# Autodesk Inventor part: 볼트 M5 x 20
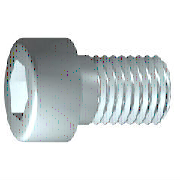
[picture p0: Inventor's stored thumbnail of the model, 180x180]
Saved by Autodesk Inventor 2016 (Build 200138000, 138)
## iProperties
Created: 2012-02
Part Number: 볼트 M5 x 20
Material: 스테인리스강
Description: 6각 소켓 머리 캡 나사
Document SubType Name: Modeling
Standard: ISO 4762
Designer: mduedu
Standard Revision: Fourth edition 2004-03-01
Standards Organization: ISO
Language: ko-KR
Size Designation: M5 x 20
Categories: <MemberInstance><Categories><Category DisplayName="조임쇠" InternalName="e4da775c-781d-43d5-af7c-5136215cf5a6" Mnemonic="FSTN"><Category DisplayName="볼트" InternalN
Density: 8.08 g/cm^3
Mass: 5.10181 g
Surface Area: 5.88237 cm^2
Volume: 0.631412 cm^3
Appearance: 반광택
IsCustomPart: 0
Author: mduedu
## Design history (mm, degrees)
sketch "스케치1"
  geometry: L1 (-1.167, 0)-(20, 0); L2 (20, 0)-(20, 2.5); L3 (20, 2.5)-(2, 2.5); L4 (2, 2.5)-(1.509, 2.5); L5 (1.509, 2.5)-(0, 2.5); L6 (0, 2.5)-(0, 4.25); L7 (0, 4.25)-(-5, 4.25); L8 (-5, 4.25)-(-5, 2.309); L9 (-5, 2.309)-(-2.5, 2.309); L10 (-2.5, 2.309)-(-1.167, 0); L11 (-10, 0)-(25, 0) reference; L12 (0, -0.85)-(0, 5.1) reference; L13 (2, 2.5)-(0, 2.5)
  constraints: 22 end point, 6 parallel, 2 collinear, 2 perpendicular, 1 horizontal, 1 point on line
  dimensions: "d1" = 18 distance from line of L3.end L2 (= GEL); "d2" = 0.49086 distance of L4.end L3.end (computed from GAL); "d3" = 5 distance between parallel lines of L8 L6 (= KOH); "d4" = 2.5 distance of L8.end L9.end (= INTI); "d5" = 60 deg angle of L10 L1; "d6" = 5 diameter of L3 L1 (= GD); "d7" = 5 diameter of L5 L1 (= BDM); "d8" = 4.6188 diameter of L9 L1 (= 1.1547 x SW); "d9" = 8.5 diameter of L7 L1 (= KOD); "d26" = 20 distance between parallel lines of L12 L2 (= NLG)
revolve "본체" sketch "스케치1" stored, may be unused: angle "d10" = 90 deg
sketch "스케치2"
  geometry: L1 (0, -5.95)-(0, 5.95) reference; L2 (-5.95, 0)-(5.95, 0) reference; L3 (2.309, 0)-(1.155, -2); L4 (1.155, -2)-(-1.155, -2); L5 (-1.155, -2)-(-2.309, 0); L6 (-2.309, 0)-(-1.155, 2); L7 (-1.155, 2)-(1.155, 2); L8 (1.155, 2)-(2.309, 0); 2 further points
  constraints: 12 end point, 1 coincident, 1 horizontal alignment, 1 point on line, 12 other
extrude "슬롯" join sketch "스케치2" stored distance "d11" = 10; taper "d12" = 0 deg
workplane "Work Plane1"
fillet "Fillet2" dims "d30" = 0.1 (= R)
body "Solid1"
fillet "모깎기1" dims "d17" = 0.5 (= RR)
feature "스레드" dims "d13" = 18 (= GEL), "d14" = 0
chamfer "모따기1" distance "d15" = 0.49076 (= -0.5 x SPD + 0.5 x GD); stored, may be unused: second distance "d16" = 0.49076 (= GUL), angle "d27" = 45 deg
other parameters: "GD" = 5 [user parameter; used in 2 equation terms], "NLG" = 20 [user parameter; used in 1 equation term], "GEL" = 18 [user parameter; used in 2 equation terms], "KOD" = 8.5 [user parameter; used in 1 equation term], "KOH" = 5 [user parameter; used in 1 equation term], "INTI" = 2.5 [user parameter; used in 1 equation term], "GAL" = 0.49076 (= 0.61345 x PTC) [user parameter; used in 1 equation term], "GUL" = 0.49076 (= 0.61345 x PTC) [user parameter; used in 1 equation term], "BDM" = 5 (= NND) [user parameter; used in 1 equation term], "SW" = 4 [user parameter; used in 2 equation terms], "RR" = 0.5 [user parameter; used in 1 equation term], "SPD" = 4.01848 (= NND - 1.2269 x PTC) [user parameter; used in 1 equation term], "d19" = 0, "d28" = 0, "d29" = 0, "R" = 0.1 [user parameter; used in 1 equation term], "TOA" = 30 deg [user parameter], "GD1" = 4.01848 (= THREADDIA - 1.2269 x PTC) [user parameter], "THREADDIA" = 5 [user parameter; used in 1 equation term], "FAWI" = 45 deg [user parameter], "TPU" = 12.5 (computed from PTC) [user parameter], "PTC" = 0.8 [user parameter; used in 5 equation terms], "NND" = 5 [user parameter; used in 2 equation terms], "E0" = 4.62 (= 1.155 x SW) [user parameter]
